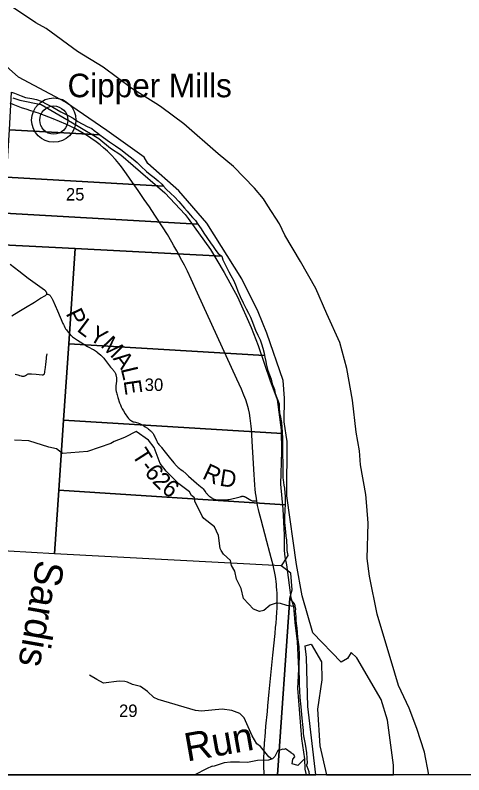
# Model space of a CAD drawing. Extents: x 0 to 34, y 0 to 22.
# Drawn here: x 28.495 to 30.002, y 14.1 to 16.649 of the extents above; entities that cross this region are included whole.
import ezdxf

# ---------------------------------------------------------------- set-up
doc = ezdxf.new("R2010")
doc.units = 0
for name, color, linetype in [('Default', 7, 'Continuous'), ('GM_X_County_Road', 7, 'Continuous'), ('GM_X_Major_River', 7, 'Continuous'), ('GM_X_Minor_River', 7, 'Continuous'), ('GM_X_Minor_River_Text', 7, 'Continuous'), ('GM_X_Section', 7, 'Continuous'), ('GM_X_Section_Text', 7, 'Continuous'), ('GM_X_State_Route', 7, 'Continuous'), ('GM_X_Township_Road', 7, 'Continuous'), ('GM_X_Township_Road_Text', 7, 'Continuous'), ('GM_X_Unincorporated', 7, 'Continuous'), ('GM_X_Unincorporated_Location', 7, 'Continuous'), ('GM_X_Unincorporated_Text', 7, 'Continuous'), ('SH_Data', 7, 'Continuous'), ('SH_Text', 7, 'Continuous')]:
    doc.layers.add(name, color=color, linetype=linetype)

msp = doc.modelspace()

# ---------------------------------------------------------------- linework, layer by layer
at = {"layer": 'Default'}
msp.add_lwpolyline([(26.2331, 14.1), (29.5051, 14.1), (29.4777, 14.3293), (29.4735, 14.4942), (29.4693, 14.5333), (29.4894, 14.5386), (29.5241, 14.4794), (29.5245, 14.4192), (29.5102, 14.3206), (29.5185, 14.1967), (29.5406, 14.1), (29.7658, 14.1), (29.7653, 14.1327), (29.7456, 14.2831), (29.7237, 14.3525), (29.6421, 14.4931), (29.6228, 14.5102), (29.6107, 14.4901), (29.5899, 14.4783), (29.495, 14.5761), (29.4584, 14.7004), (29.4395, 14.8058), (29.4078, 15.0362), (29.4089, 15.2182), (29.4051, 15.2401), (29.3983, 15.2845), (29.3998, 15.3637), (29.3953, 15.4237), (29.3397, 15.5819), (29.3107, 15.6537), (29.2566, 15.7649), (29.1391, 15.9516), (29.0449, 16.0594), (28.941, 16.1516), (28.9285, 16.1725), (28.8026, 16.2628), (28.6643, 16.3573), (28.5059, 16.4411), (28.3687, 16.5634)], dxfattribs=at)
for points in [[(28.345, 14.1), (29.3762, 14.1), (29.4168, 14.6926), (29.4251, 14.7203), (29.4211, 14.7771), (29.4209, 14.7772), (29.388, 14.8008), (28.6267, 14.8415), (28.3943, 14.8549), (28.3788, 14.6076), (28.3627, 14.3611), (28.3456, 14.1084)], [(29.3762, 14.1), (29.4839, 14.1), (29.4818, 14.1101), (29.476, 14.1279), (29.4745, 14.1294), (29.4741, 14.1316), (29.4741, 14.1332), (29.4764, 14.1407), (29.4759, 14.1555), (29.4743, 14.1737), (29.4697, 14.2029), (29.4654, 14.2256), (29.4635, 14.2373), (29.4627, 14.2483), (29.4619, 14.2585), (29.4588, 14.2903), (29.4556, 14.3286), (29.4525, 14.3597), (29.45, 14.4044), (29.4491, 14.465), (29.4493, 14.5025), (29.4489, 14.529), (29.4446, 14.5612), (29.4426, 14.579), (29.4418, 14.5923), (29.4402, 14.6082), (29.4391, 14.6176), (29.4383, 14.6317), (29.4367, 14.6491), (29.437, 14.6563), (29.4355, 14.6638), (29.4347, 14.6676), (29.4328, 14.6741), (29.4168, 14.6926)]]:
    msp.add_lwpolyline(points, close=True, dxfattribs=at)
at = {"layer": 'GM_X_County_Road'}
msp.add_lwpolyline([(28.4834, 15.64), (28.5073, 15.6547), (28.5299, 15.6688), (28.5595, 15.6863), (28.5805, 15.6996), (28.5968, 15.7087), (28.5983, 15.7098), (28.5994, 15.7108), (28.6003, 15.712), (28.6009, 15.7133), (28.6011, 15.7148), (28.6011, 15.716), (28.6009, 15.7173), (28.6005, 15.7185), (28.6, 15.7195), (28.5992, 15.7207), (28.5985, 15.7217), (28.5975, 15.7227), (28.5965, 15.7237), (28.5952, 15.7249), (28.5931, 15.7266), (28.5859, 15.7317), (28.5618, 15.7483), (28.5391, 15.7653), (28.5076, 15.7901), (28.4779, 15.8128)], dxfattribs=at)
at = {"layer": 'GM_X_Major_River'}
for points in [[(29.6281, 15.3578), (29.6085, 15.4639), (29.5851, 15.5504), (29.5416, 15.6474), (29.5043, 15.7315), (29.4529, 15.8224), (29.4007, 15.9114), (29.3824, 15.9493), (29.3433, 16.0099), (29.3292, 16.033), (29.2992, 16.0689), (29.2282, 16.1419), (29.1766, 16.1842), (29.0609, 16.2847), (28.9874, 16.3394), (28.9764, 16.3474), (28.8873, 16.4036), (28.791, 16.4746), (28.7046, 16.5274), (28.5988, 16.6044), (28.5643, 16.6232), (28.4142, 16.724)], [(28.4875, 16.372), (28.5106, 16.3645), (28.5821, 16.3492), (28.7014, 16.2802), (28.7761, 16.2357), (28.8155, 16.2025), (28.8493, 16.1806), (28.8914, 16.1451), (28.9972, 16.0536), (29.0655, 15.9799), (29.0758, 15.967), (29.1514, 15.8625), (29.1967, 15.7857), (29.2413, 15.7042), (29.2874, 15.6015), (29.3107, 15.5409), (29.3508, 15.4217), (29.3752, 15.359)], [(29.3752, 15.359), (29.3886, 15.2578), (29.3897, 15.1853), (29.3865, 15.0756), (29.3934, 14.9918), (29.3988, 14.9058), (29.3983, 14.853), (29.4, 14.831), (29.4061, 14.8049), (29.4207, 14.6942), (29.43, 14.6651), (29.434, 14.6112), (29.442, 14.5471), (29.4459, 14.4554), (29.4442, 14.411), (29.4436, 14.3912), (29.4562, 14.2206), (29.4664, 14.1539), (29.4677, 14.1186), (29.4723, 14.1)], [(29.8837, 14.1), (29.8698, 14.1757), (29.8436, 14.2556), (29.8179, 14.3241), (29.7823, 14.4001), (29.77, 14.4406), (29.7103, 14.6394), (29.6847, 14.7664), (29.6775, 14.8255), (29.6803, 14.9443), (29.6762, 15.0019), (29.6722, 15.0409), (29.6547, 15.1406), (29.6518, 15.1869), (29.6405, 15.2498), (29.6281, 15.3578)]]:
    msp.add_lwpolyline(points, dxfattribs=at)
at = {"layer": 'GM_X_Minor_River'}
for points in [[(29.43, 14.6651), (29.4067, 14.6677), (29.3865, 14.6751), (29.371, 14.676), (29.3512, 14.6698), (29.3298, 14.6511), (29.315, 14.6478), (29.2948, 14.6564), (29.2619, 14.692), (29.2542, 14.7249), (29.2385, 14.7566), (29.2325, 14.783), (29.2214, 14.8019), (29.2181, 14.8195), (29.195, 14.8404), (29.187, 14.8531), (29.1831, 14.8593), (29.1776, 14.9036), (29.1641, 14.9317), (29.129, 14.9598), (29.1229, 14.968), (29.0987, 15.0185), (29.0968, 15.0296), (29.0872, 15.0375), (29.08, 15.0499), (29.0445, 15.076), (29.0023, 15.1188), (28.9819, 15.1449), (28.9613, 15.1979), (28.9431, 15.2232), (28.9013, 15.2526), (28.8648, 15.2333), (28.8564, 15.2298), (28.8269, 15.2189), (28.8158, 15.2117), (28.7375, 15.1846), (28.6545, 15.1781), (28.6342, 15.1936), (28.6075, 15.199), (28.5405, 15.2213), (28.4933, 15.2231)], [(29.3564, 14.1524), (29.3471, 14.1607), (29.3183, 14.195), (29.3065, 14.2042), (29.2903, 14.2313), (29.2637, 14.291), (29.2494, 14.3058), (29.2221, 14.3158), (29.1902, 14.3206), (29.1204, 14.3141), (29.1001, 14.3155), (28.9757, 14.3522), (28.9611, 14.3591), (28.9395, 14.3799), (28.9154, 14.3966), (28.8895, 14.4032), (28.872, 14.4109), (28.8638, 14.4131), (28.8445, 14.4145), (28.7918, 14.407), (28.7687, 14.4199), (28.745, 14.4343)], [(29.3805, 14.1822), (29.3775, 14.1811), (29.3673, 14.1617), (29.3586, 14.1534), (29.3457, 14.1491), (29.3091, 14.1479), (29.2754, 14.1418), (29.2482, 14.1421), (29.2184, 14.1428), (29.1964, 14.1397), (29.1594, 14.1274), (29.156, 14.1285), (29.1379, 14.1205), (29.0979, 14.1)], [(29.3797, 14.1819), (29.3915, 14.1857)], [(29.4215, 14.1737), (29.4028, 14.1873), (29.3971, 14.185), (29.3915, 14.1857)], [(29.4664, 14.1539), (29.444, 14.1315), (29.4248, 14.1364), (29.4278, 14.1528), (29.4342, 14.1608), (29.4311, 14.1687), (29.4212, 14.1738)]]:
    msp.add_lwpolyline(points, dxfattribs=at)
at = {"layer": 'GM_X_Section'}
for points in [[(28.4755, 16.264), (28.4829, 16.3911), (28.4923, 16.3873), (28.5154, 16.3787), (28.5302, 16.3735), (28.5507, 16.3697), (28.5662, 16.366), (28.5825, 16.3608), (28.6011, 16.351), (28.6213, 16.3401), (28.6482, 16.325), (28.6748, 16.3111), (28.6896, 16.3032), (28.7055, 16.2926), (28.7367, 16.2757), (28.7519, 16.2685), (28.7606, 16.2625), (28.7731, 16.2534), (28.7796, 16.2482)], [(28.4755, 16.264), (28.7796, 16.2482), (28.7914, 16.2387), (28.8122, 16.224), (28.832, 16.2108), (28.8495, 16.1988), (28.8711, 16.1814), (28.8909, 16.1659), (28.9042, 16.155), (28.9175, 16.1429), (28.9361, 16.1244), (28.9479, 16.115), (28.9619, 16.1048), (28.9752, 16.0935), (28.987, 16.0825), (28.9934, 16.0755), (28.4664, 16.1061)], [(28.9934, 16.0755), (29.0026, 16.0652), (29.0175, 16.0512), (29.0304, 16.0395), (29.0444, 16.0236), (29.0635, 16.0021), (29.073, 15.9919), (29.0829, 15.9794), (29.0901, 15.9704), (29.1, 15.9598), (29.1085, 15.9479), (28.4594, 15.9845), (28.4664, 16.1061)], [(28.4594, 15.9845), (29.1085, 15.9479), (29.1198, 15.9322), (29.1285, 15.9182), (29.151, 15.885), (29.1594, 15.8732), (29.1693, 15.86), (29.1769, 15.8494), (29.1887, 15.8408), (28.6965, 15.8662), (28.4533, 15.8787)], [(28.4533, 15.8787), (28.6965, 15.8662), (28.6747, 15.5464), (28.6572, 15.29), (28.6412, 15.0549), (28.6267, 14.8415), (28.3943, 14.8549), (28.4095, 15.1186), (28.4242, 15.3738), (28.439, 15.6312)], [(28.6965, 15.8662), (29.1887, 15.8408), (29.1921, 15.8283), (29.1971, 15.8196), (29.2051, 15.8041), (29.2124, 15.7878), (29.2196, 15.7753), (29.2288, 15.7579), (29.2375, 15.7386), (29.2429, 15.7235), (29.2502, 15.7049), (29.2605, 15.6841), (29.2711, 15.6637), (29.2788, 15.6497), (29.2856, 15.6357), (29.2898, 15.6244), (29.3025, 15.5918), (29.3101, 15.5752), (29.3173, 15.5597), (29.3223, 15.5464), (29.3262, 15.5313), (29.3308, 15.515), (29.3323, 15.5072), (28.6747, 15.5464)], [(29.3323, 15.5072), (29.3335, 15.5014), (29.3365, 15.4866), (29.3373, 15.4794), (29.3438, 15.4567), (29.3488, 15.4427), (29.3542, 15.428), (29.3584, 15.4117), (29.3653, 15.3931), (29.3676, 15.3799), (29.3812, 15.3449), (29.3816, 15.3294), (29.3824, 15.3184), (29.3828, 15.315), (29.3863, 15.3002), (29.3894, 15.2824), (29.3914, 15.2495), (29.3916, 15.2458), (28.6572, 15.29), (28.6747, 15.5464)], [(28.6572, 15.29), (29.3916, 15.2458), (29.3922, 15.2339), (29.393, 15.212), (29.3923, 15.1968), (29.3924, 15.1896), (29.3928, 15.1832), (29.3937, 15.1385), (29.3942, 15.1028), (29.3942, 15.0968), (29.395, 15.0903), (29.3973, 15.0722), (29.3989, 15.0623), (29.3996, 15.0593), (29.4012, 15.0339), (29.4017, 15.0123), (29.4014, 15.0063), (28.6412, 15.0549)], [(29.4014, 15.0063), (29.4006, 14.9903), (29.3992, 14.9627), (29.3993, 14.9464), (29.4012, 14.9267), (29.4044, 14.9017), (29.4051, 14.893), (29.4063, 14.8903), (29.4072, 14.8589), (29.4072, 14.8532), (29.411, 14.8365), (29.405, 14.8267), (29.3903, 14.8042), (29.388, 14.8008), (28.6267, 14.8415), (28.6412, 15.0549)]]:
    msp.add_lwpolyline(points, close=True, dxfattribs=at)
at = {"layer": 'GM_X_State_Route'}
for points in [[(28.5314, 16.3337), (28.5275, 16.3349), (28.5163, 16.3388), (28.4994, 16.3451), (28.4885, 16.3494), (28.4785, 16.3537)], [(29.331, 14.1), (29.3306, 14.1136), (29.3305, 14.1192), (29.3305, 14.1247), (29.3304, 14.1341), (29.3304, 14.139), (29.3304, 14.145), (29.3304, 14.1489), (29.3304, 14.1558), (29.3305, 14.1601), (29.3305, 14.1632), (29.3307, 14.1691), (29.3308, 14.1756), (29.331, 14.18), (29.3311, 14.1819), (29.3312, 14.1843), (29.3313, 14.1868), (29.3315, 14.1918), (29.3317, 14.1967), (29.332, 14.2016), (29.3322, 14.204), (29.3325, 14.207), (29.3328, 14.2112), (29.3331, 14.2142), (29.3336, 14.2198), (29.3342, 14.2259), (29.3372, 14.2631), (29.3421, 14.3125), (29.344, 14.3317), (29.3483, 14.3781), (29.3603, 14.5013), (29.3676, 14.5747), (29.3694, 14.5945), (29.3709, 14.6093), (29.3726, 14.6272), (29.374, 14.6458), (29.3746, 14.6592), (29.3752, 14.6737), (29.3753, 14.6898), (29.3751, 14.7016), (29.3746, 14.7109), (29.3741, 14.7201), (29.3731, 14.7317), (29.3725, 14.7393), (29.3714, 14.7481), (29.3702, 14.7584), (29.3678, 14.7716), (29.3658, 14.7822), (29.3636, 14.7925), (29.3613, 14.8034), (29.3581, 14.8163), (29.355, 14.8287), (29.3506, 14.8454), (29.3404, 14.8833), (29.3208, 14.9553), (29.3145, 14.98), (29.3121, 14.9906), (29.309, 15.0042), (29.3061, 15.0199), (29.3038, 15.0349), (29.3024, 15.0464), (29.3012, 15.0587), (29.3001, 15.0718), (29.2989, 15.0907), (29.2979, 15.107), (29.2943, 15.1633), (29.292, 15.2011), (29.2883, 15.2594), (29.2874, 15.2701), (29.2867, 15.2791), (29.2844, 15.297), (29.2815, 15.3135), (29.2781, 15.3286), (29.2739, 15.3441), (29.2691, 15.3589), (29.2633, 15.3745), (29.2549, 15.3946), (29.2398, 15.428), (29.1078, 15.7167), (29.0862, 15.7636), (29.0736, 15.7898), (29.0639, 15.8099), (29.055, 15.8257), (29.0374, 15.8585), (29.0279, 15.8754), (29.021, 15.8878), (29.0061, 15.9129), (28.9896, 15.9392), (28.9643, 15.9783), (28.9456, 16.0061), (28.9284, 16.0311), (28.9079, 16.0609), (28.8914, 16.0846), (28.8771, 16.1053), (28.8636, 16.1247), (28.8519, 16.1407), (28.843, 16.1518), (28.8316, 16.1649), (28.8172, 16.1803), (28.8049, 16.1925), (28.792, 16.2042), (28.7801, 16.2141), (28.7673, 16.2239), (28.7492, 16.2369), (28.7383, 16.244), (28.7186, 16.2558), (28.6974, 16.2676), (28.6814, 16.2758), (28.6651, 16.2833), (28.6227, 16.301), (28.5937, 16.3122), (28.5787, 16.318), (28.5729, 16.3201), (28.5659, 16.3226), (28.556, 16.326), (28.5477, 16.3287), (28.5314, 16.3337)]]:
    msp.add_lwpolyline(points, dxfattribs=at)
at = {"layer": 'GM_X_Township_Road'}
for points in [[(28.6009, 15.7133), (28.6032, 15.7129), (28.6052, 15.7125), (28.6067, 15.712), (28.6081, 15.7114), (28.6095, 15.7105), (28.611, 15.7094), (28.6124, 15.7081), (28.6136, 15.7067), (28.6148, 15.7052), (28.6161, 15.7034), (28.6174, 15.7012), (28.6186, 15.6992), (28.6198, 15.6969), (28.6208, 15.6948), (28.6219, 15.6927), (28.6294, 15.6753), (28.6373, 15.6568), (28.6552, 15.6151), (28.6571, 15.611), (28.6593, 15.6067), (28.6622, 15.6013), (28.6645, 15.5972), (28.6673, 15.5929), (28.6695, 15.5898), (28.6725, 15.586), (28.6758, 15.582), (28.6798, 15.5774), (28.6825, 15.5748), (28.685, 15.5722), (28.6877, 15.5699), (28.6909, 15.5674), (28.6944, 15.5649), (28.7045, 15.5585), (28.7222, 15.5469), (28.7328, 15.5404), (28.7377, 15.5375), (28.7426, 15.5349), (28.7551, 15.5286), (28.7582, 15.5269), (28.7617, 15.5248), (28.765, 15.5225), (28.7677, 15.5205), (28.7702, 15.5185), (28.7824, 15.5085), (28.7851, 15.5062), (28.7876, 15.5037), (28.7898, 15.5013), (28.7922, 15.4985), (28.7949, 15.4951), (28.8154, 15.4676), (28.8205, 15.4622), (28.8226, 15.4603), (28.8246, 15.458), (28.8266, 15.4556), (28.828, 15.4537), (28.8295, 15.4513), (28.8306, 15.4491), (28.8316, 15.4464), (28.8326, 15.4437), (28.8334, 15.4412), (28.834, 15.4388), (28.8345, 15.4365), (28.8348, 15.4342), (28.8351, 15.4316), (28.8353, 15.4292), (28.8353, 15.4267), (28.8352, 15.424), (28.8349, 15.4206), (28.8333, 15.4056), (28.8331, 15.4033), (28.833, 15.4007), (28.8331, 15.3983), (28.8331, 15.3962), (28.8333, 15.3939), (28.8335, 15.3912), (28.8339, 15.3885), (28.8343, 15.3859), (28.8349, 15.3832), (28.8359, 15.379), (28.837, 15.375), (28.8397, 15.3658), (28.8457, 15.3481), (28.8484, 15.3413), (28.8515, 15.3344), (28.8546, 15.3286), (28.8585, 15.3215), (28.8642, 15.3115), (28.8668, 15.3077), (28.8695, 15.304), (28.8725, 15.3002), (28.8759, 15.2959), (28.8787, 15.2929), (28.8804, 15.2912), (28.8824, 15.2896), (28.8851, 15.2878), (28.888, 15.2863), (28.8914, 15.2851), (28.8948, 15.2843), (28.8987, 15.2833), (28.9027, 15.2822), (28.9071, 15.2808), (28.9123, 15.2787), (28.919, 15.2754), (28.9254, 15.2718), (28.9317, 15.2678), (28.9392, 15.2629), (28.9428, 15.2602), (28.946, 15.2578), (28.9488, 15.2555), (28.9512, 15.2534), (28.9529, 15.2517), (28.9543, 15.2502), (28.9556, 15.2487), (28.9568, 15.2469), (28.9579, 15.245), (28.9591, 15.2429), (28.9606, 15.2403), (28.9622, 15.2373), (28.9636, 15.2344), (28.9694, 15.2216), (28.9714, 15.218), (28.9734, 15.2144), (28.9753, 15.2118), (28.9778, 15.209), (28.9833, 15.2028), (28.985, 15.2005), (28.9867, 15.1982), (28.9987, 15.1824), (29.0121, 15.1657), (29.0274, 15.1471), (29.0368, 15.1373), (29.0394, 15.1346), (29.0424, 15.1317), (29.0453, 15.1292), (29.0491, 15.1261), (29.0576, 15.1196), (29.0693, 15.1095), (29.0773, 15.1025), (29.1034, 15.0789), (29.1116, 15.0721), (29.1224, 15.0631), (29.1236, 15.0622), (29.1244, 15.0614), (29.1252, 15.0606), (29.1262, 15.0593), (29.1315, 15.0516), (29.135, 15.0471), (29.1365, 15.0453), (29.1381, 15.0435), (29.1401, 15.0414), (29.1423, 15.0392), (29.1443, 15.0375), (29.1465, 15.0356), (29.1488, 15.0341), (29.1518, 15.032), (29.1547, 15.03), (29.1572, 15.0282), (29.1596, 15.0267), (29.1618, 15.0255), (29.1636, 15.0247), (29.1658, 15.024), (29.1682, 15.0235), (29.1707, 15.0231), (29.1736, 15.0229), (29.177, 15.0226), (29.1807, 15.0224), (29.1847, 15.0223), (29.1994, 15.0226), (29.2048, 15.0229), (29.2096, 15.0234), (29.2141, 15.0241), (29.2184, 15.0248), (29.2228, 15.0257), (29.2275, 15.0268), (29.2326, 15.0281), (29.2504, 15.0332), (29.2529, 15.0339), (29.2549, 15.0343), (29.2567, 15.0346), (29.2586, 15.0347), (29.2605, 15.0347), (29.2625, 15.0344), (29.2647, 15.0339), (29.2663, 15.0334), (29.2677, 15.0328), (29.2693, 15.032), (29.2869, 15.0218), (29.2887, 15.0209), (29.2905, 15.02), (29.2923, 15.0194), (29.2939, 15.0191), (29.2955, 15.0189), (29.2974, 15.0189), (29.2996, 15.019), (29.3061, 15.0199)], [(28.495, 15.4444), (28.4993, 15.4434), (28.5036, 15.4423), (28.5069, 15.4413), (28.5099, 15.4403), (28.5146, 15.4388), (28.517, 15.4381), (28.5192, 15.4377), (28.5213, 15.4375), (28.5235, 15.4377), (28.5256, 15.4383), (28.5274, 15.439), (28.5294, 15.44), (28.5331, 15.4423), (28.5348, 15.4434), (28.5366, 15.4443), (28.5388, 15.4452), (28.5412, 15.4458), (28.5436, 15.4461), (28.5464, 15.4461), (28.55, 15.4459), (28.566, 15.4445), (28.5859, 15.4427), (28.5873, 15.4427), (28.5888, 15.4427), (28.5899, 15.4429), (28.5908, 15.4433), (28.5917, 15.4439), (28.5925, 15.4448), (28.5931, 15.4459), (28.5935, 15.4469), (28.5939, 15.4482), (28.5945, 15.4505), (28.5951, 15.4543), (28.5957, 15.4591), (28.5977, 15.4775), (28.6, 15.4973), (28.6003, 15.4995), (28.6007, 15.502), (28.6023, 15.5128)]]:
    msp.add_lwpolyline(points, dxfattribs=at)
at = {"layer": 'GM_X_Unincorporated'}
for radius in [0.0744, 0.0472]:
    msp.add_circle((28.6247, 16.2973), radius, dxfattribs=at)
at = {"layer": 'GM_X_Unincorporated_Location'}
msp.add_line((28.6247, 16.2973), (28.6247, 16.2973), dxfattribs=at)
at = {"layer": 'SH_Data'}
msp.add_lwpolyline([(23.5167, 20.9), (30.3167, 20.9), (30.3167, 14.1), (23.5167, 14.1)], close=True, dxfattribs=at)
at = {"layer": 'SH_Text'}
msp.add_lwpolyline([(23.5167, 14.1), (29.5051, 14.1), (29.4777, 14.3293), (29.4735, 14.4942), (29.4693, 14.5333), (29.4894, 14.5386), (29.5241, 14.4794), (29.5245, 14.4192), (29.5102, 14.3206), (29.5185, 14.1967), (29.5406, 14.1), (29.7658, 14.1), (29.7653, 14.1327), (29.7456, 14.2831), (29.7237, 14.3525), (29.6421, 14.4931), (29.6228, 14.5102), (29.6107, 14.4901), (29.5899, 14.4783), (29.495, 14.5761), (29.4584, 14.7004), (29.4395, 14.8058), (29.4078, 15.0362), (29.4089, 15.2182), (29.4051, 15.2401), (29.3983, 15.2845), (29.3998, 15.3637), (29.3953, 15.4237), (29.3397, 15.5819), (29.3107, 15.6537), (29.2566, 15.7649), (29.1391, 15.9516), (29.0449, 16.0594), (28.941, 16.1516), (28.9285, 16.1725), (28.8026, 16.2628), (28.6643, 16.3573), (28.5059, 16.4411), (28.3687, 16.5634)], dxfattribs=at)

# ---------------------------------------------------------------- texts
at = {"layer": 'GM_X_Minor_River_Text'}
for s, height, rotation, p in [('Sardis', 0.0947, 259.9987, (28.5676, 14.8245)), ('Run', 0.09469, 10.0015, (29.0722, 14.1444))]:
    msp.add_text(s, height=height, rotation=rotation, dxfattribs=at).set_placement(p)
at = {"layer": 'GM_X_Section_Text'}
for s, p in [('25', (28.6654, 16.0273)), ('30', (28.93, 15.3881)), ('29', (28.8437, 14.294))]:
    msp.add_text(s, height=0.04186, rotation=0, dxfattribs=at).set_placement(p)
at = {"layer": 'GM_X_Township_Road_Text'}
for s, rotation, p in [('P', 295.7406, (28.664, 15.6483)), ('L', 323.2377, (28.6994, 15.591)), ('Y', 330.0747, (28.7397, 15.5615)), ('M', 314.386, (28.7798, 15.5391)), ('A', 307.4309, (28.8217, 15.4964)), ('L', 283.3986, (28.8494, 15.4623)), ('E', 278.2483, (28.859, 15.4223)), ('T', 302.5192, (28.8855, 15.1737)), ('-', 309.2461, (28.9126, 15.132)), ('R', 334.8856, (29.1203, 15.0955)), ('6', 308.9817, (28.9273, 15.114)), ('D', 351.2587, (29.1792, 15.0706)), ('2', 314.3218, (28.9532, 15.0825)), ('6', 321.8031, (28.9836, 15.052))]:
    msp.add_text(s, height=0.0568, rotation=rotation, dxfattribs=at).set_placement(p)
at = {"layer": 'GM_X_Unincorporated_Text'}
msp.add_text('Cipper Mills', height=0.078977, rotation=0, dxfattribs=at).set_placement((28.6708, 16.3739))

doc.saveas('drawing.dxf')
